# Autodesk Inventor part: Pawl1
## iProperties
Created: 2010-09
Part Number: Pawl1
Document SubType Name: Modeling
Designer: nguyenducthang
Density: 1 g/cm^3
Mass: 0.118759 g
Surface Area: 2.00914 cm^2
Volume: 0.118759 cm^3
Author: nguyenducthang
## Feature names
1. Extrusion5
2. Extrusion6
3. Extrusion7
4. Fillet1
